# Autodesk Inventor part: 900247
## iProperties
Created: 2007-12
Part Number: 900247
Document SubType Name: Modeling
Designer: DV
Density: 1.13 g/cm^3
Material: Nylon Composite (Nylon, molybdenum disulphide)
Description: WIRE MOUNTING TAB - STRAIGHT
Mass: 0.768729 g
Surface Area: 12.6483 cm^2
Volume: 0.680291 cm^3
Component Category: Electrical
Author: DV
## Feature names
1. Extrusion1
2. Revolution1
3. Fillet1
4. Fillet2
5. Fillet3
6. Fillet4
7. Extrusion2
8. Extrusion3
